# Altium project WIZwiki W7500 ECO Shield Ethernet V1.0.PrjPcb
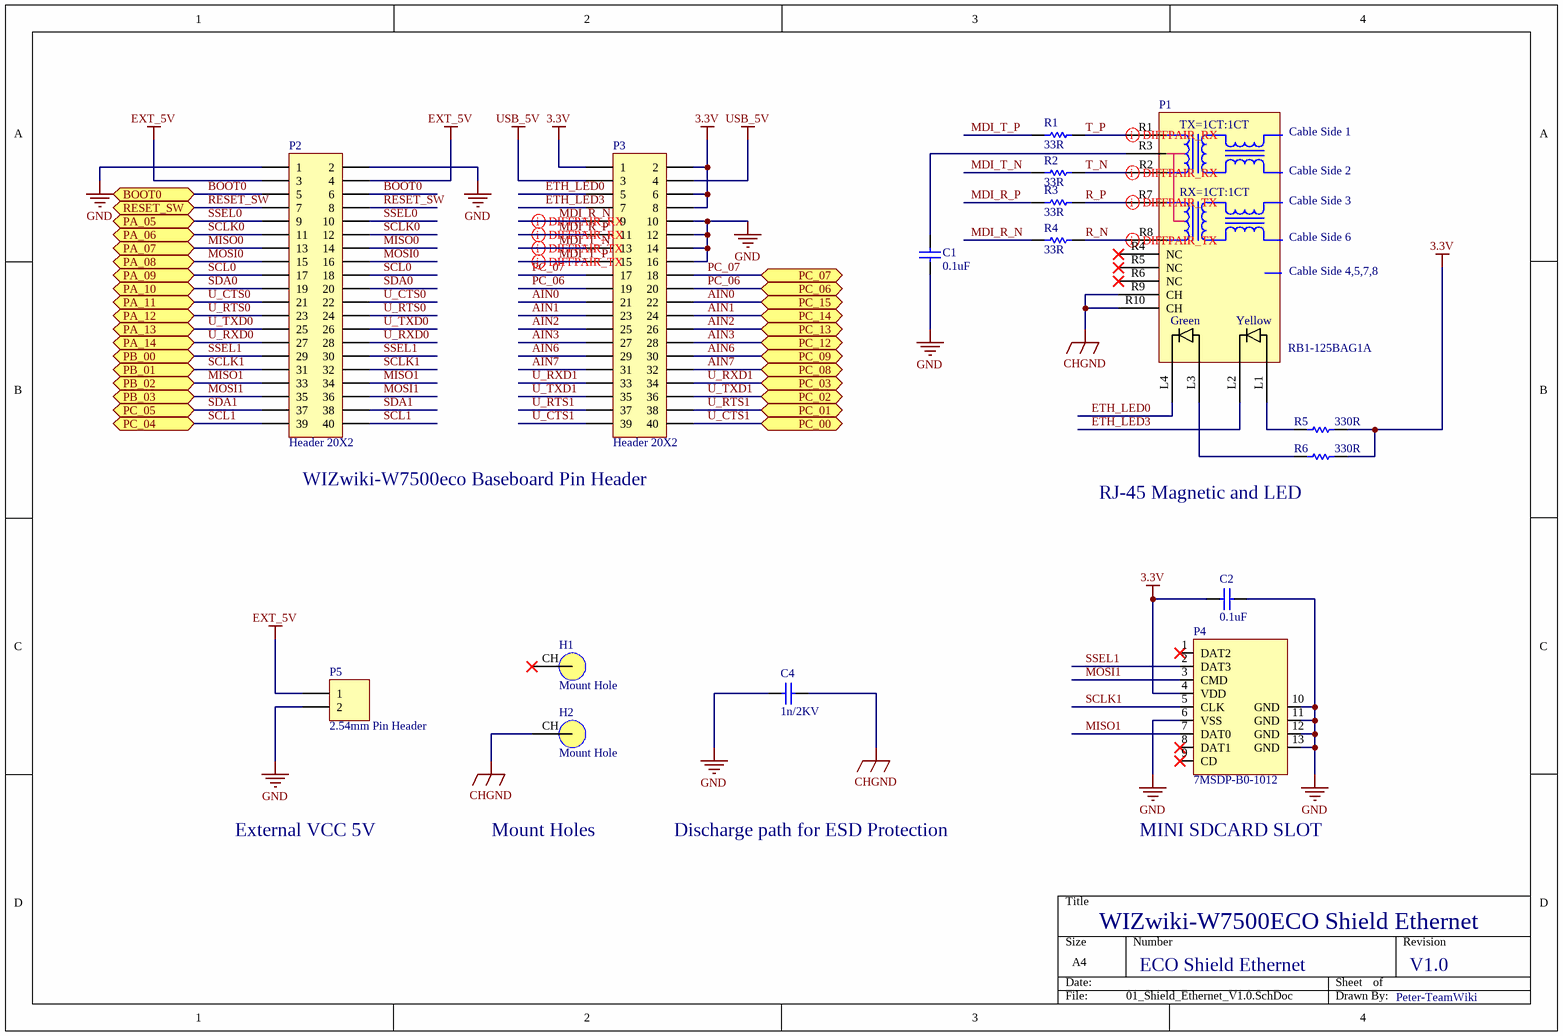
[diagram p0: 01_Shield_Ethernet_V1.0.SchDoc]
1 sheet, 16 parts. Net scope: flat (ports and power ports of the same name join across sheets).
Board file: WIZwiki W7500 ECO Shield Ethernet V1.0.PcbDoc

## Sheet 01_Shield_Ethernet_V1.0.SchDoc
size A4

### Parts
C1  0.1uF  [CAP-0603]
C2  0.1uF  [CAP-0603]
C4  1n/2KV  [CAP-1808]
H1  Mount Hole
H2  Mount Hole
P1  RB1-125BAG1A  [RJ45-125BAG1A]
P2  Header 20X2  [IDC-2X20]
P3  Header 20X2  [IDC-2X20]
P4  7MSDP-B0-1012  [7MSDP-B0-1012]
P5  2.54mm Pin Header  [IDC-1X2]
R1  33R  [RES-0603]
R2  33R  [RES-0603]
R3  33R  [RES-0603]
R4  33R  [RES-0603]
R5  330R  [RES-0603]
R6  330R  [RES-0603]

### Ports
BOOT0, PA_05, PA_06, PA_07, PA_08, PA_09, PA_10, PA_11, PA_12, PA_13, PA_14, PB_00, PB_01, PB_02, PB_03, PC_00, PC_01, PC_02, PC_03, PC_04, PC_05, PC_06, PC_07, PC_08, PC_09, PC_12, PC_13, PC_14, PC_15, RESET_SW

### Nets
3.3V: C2.2 P3.1 P3.2 P3.6 P3.8 P4.4(VDD) R5.1 R6.1
CHGND: C4.2 H2.CH P1.R9(CH) P1.R10(CH)
EXT_5V: P2.3 P2.4 P5.1
GND: C1.1 C2.1 C4.1 P2.1 P2.2 P3.10 P3.12 P3.14 P3.16 P4.6(VSS) P4.10(GND) P4.11(GND) P4.12(GND) P4.13(GND) P5.2
USB_5V: P3.3 P3.4
AIN0: P3.21 P3.22 ; port PC_15
AIN1: P3.23 P3.24 ; port PC_14
AIN2: P3.25 P3.26 ; port PC_13
AIN3: P3.27 P3.28 ; port PC_12
AIN6: P3.29 P3.30 ; port PC_09
AIN7: P3.31 P3.32 ; port PC_08
BOOT0: P2.5 P2.6 ; port BOOT0
ETH_LED0: P1.L4 P3.5
ETH_LED3: P1.L2 P3.7
MDI_R_N: P3.9 R4.1
MDI_R_P: P3.11 R3.1
MDI_T_N: P3.13 R2.1
MDI_T_P: P3.15 R1.1
MISO0: P2.13 P2.14 ; port PA_07
MISO1: P2.33 P2.34 P4.7(DAT0) ; port PB_02
MOSI0: P2.15 P2.16 ; port PA_08
MOSI1: P2.35 P2.36 P4.3(CMD) ; port PB_03
PC_06: P3.19 P3.20 ; port PC_06
PC_07: P3.17 P3.18 ; port PC_07
R_N: P1.R8 R4.2
R_P: P1.R7 R3.2
RESET_SW: P2.7 P2.8 ; port RESET_SW
SCL0: P2.17 P2.18 ; port PA_09
SCL1: P2.39 P2.40 ; port PC_04
SCLK0: P2.11 P2.12 ; port PA_06
SCLK1: P2.31 P2.32 P4.5(CLK) ; port PB_01
SDA0: P2.19 P2.20 ; port PA_10
SDA1: P2.37 P2.38 ; port PC_05
SSEL0: P2.9 P2.10 ; port PA_05
SSEL1: P2.29 P2.30 P4.2(DAT3) ; port PB_00
T_N: P1.R2 R2.2
T_P: P1.R1 R1.2
U_CTS0: P2.21 P2.22 ; port PA_11
U_CTS1: P3.39 P3.40 ; port PC_00
U_RTS0: P2.23 P2.24 ; port PA_12
U_RTS1: P3.37 P3.38 ; port PC_01
U_RXD0: P2.27 P2.28 ; port PA_14
U_RXD1: P3.33 P3.34 ; port PC_03
U_TXD0: P2.25 P2.26 ; port PA_13
U_TXD1: P3.35 P3.36 ; port PC_02
NetC1_2: C1.2 P1.R3
NetP1_L1: P1.L1 R5.2
NetP1_L3: P1.L3 R6.2

Not connected (* = marked no-connect by the designer): H1 CH*; P1 R4(NC)* R5(NC)* R6(NC)*; P4 1(DAT2)* 8(DAT1)* 9(CD)*

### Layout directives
differential pair: MDI_R_N, MDI_R_P, MDI_T_N, MDI_T_P, R_N, R_P, T_N, T_P

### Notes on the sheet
- WIZwiki-W7500eco Baseboard Pin Header
- (near R6) RJ-45 Magnetic and LED
- External VCC 5V
- Mount Holes
- Discharge path for ESD Protection
- MINI SDCARD SLOT
- WIZwiki-W7500ECO Shield Ethernet
- ECO Shield Ethernet
- V1.0
- Peter-TeamWiki

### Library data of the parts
C1 C2 = CAP-0603: Ceramic CAP 0603(1608)
C4 = CAP-1808: Ceramic CAP 1808(4520)
P1 = RJ-45 MAGNETICS AND LEDS RB1-125BAG1A
P2 P3 = Header 20X2: Header, 20-Pin, Dual row, 2.54mm
P4 = 7MSDP-B0-1012: Micro SD Card Socket
P5 = MHDR1X2: Header, 2-Pin
R1-R6 = RES-0603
